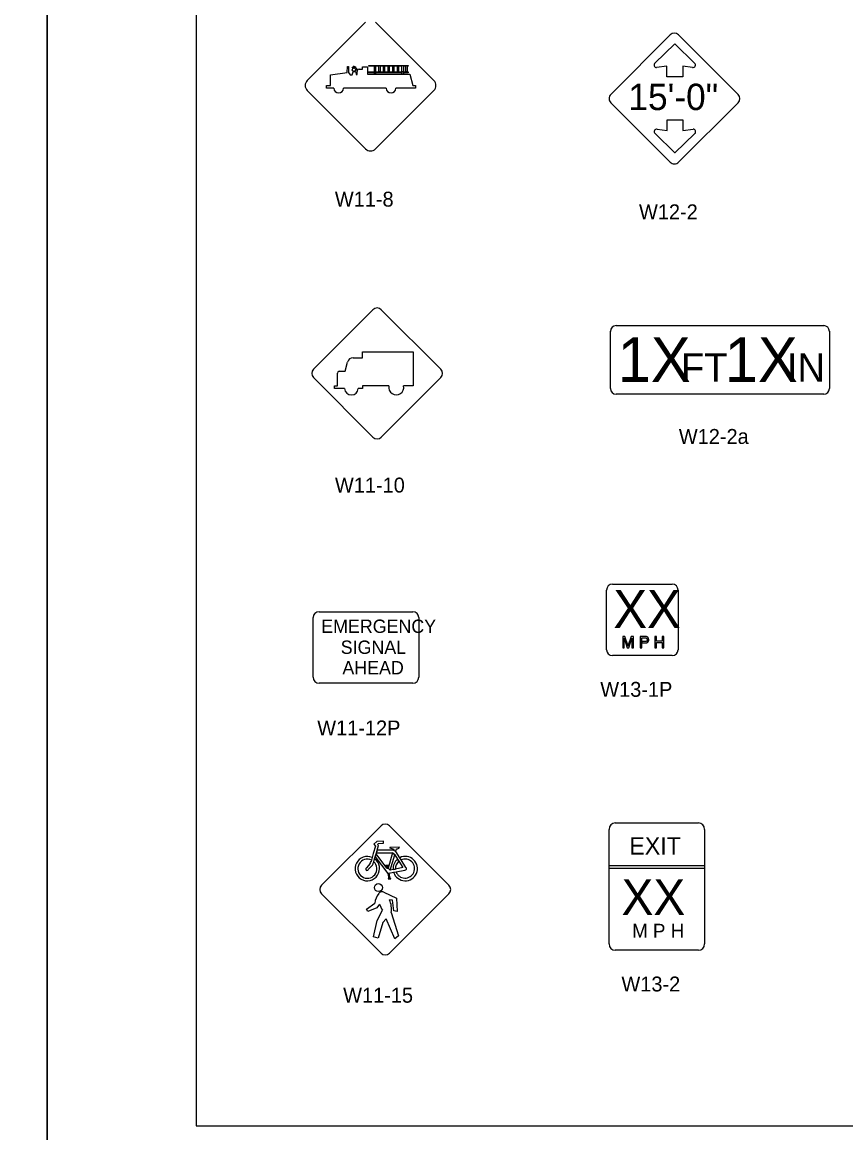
# Model space of a CAD drawing. Extents: x 42133 to 45533, y 41351 to 47951.
# Drawn here: x 43821 to 44235, y 45798 to 46356 of the extents above; entities that cross this region are included whole.
import ezdxf

# ---------------------------------------------------------------- set-up
doc = ezdxf.new("R2010")
doc.units = 0
for name, color, linetype in [('#plot_shape', 7, 'Continuous'), ('P_ODOT_PLAN_Border', 7, 'Continuous'), ('P_TRAF_SIGN_SignDetails', 7, 'Continuous')]:
    doc.layers.add(name, color=color, linetype=linetype)

msp = doc.modelspace()

# ---------------------------------------------------------------- linework, layer by layer
at = {"layer": '#plot_shape'}
for points in [[(42133.34, 45751.35), (43833.34, 45751.35), (43833.34, 46851.35), (42133.34, 46851.35)], [(43833.34, 45751.35), (45533.34, 45751.35), (45533.34, 46851.35), (43833.34, 46851.35)]]:
    msp.add_lwpolyline(points, close=True, dxfattribs=at)
at = {"layer": 'P_ODOT_PLAN_Border'}
msp.add_lwpolyline([(43908.34, 45801.35), (45508.34, 45801.35), (45508.34, 46801.35), (43908.34, 46801.35)], close=True, dxfattribs=at)
at = {"layer": 'P_TRAF_SIGN_SignDetails'}
for p, q in [((43964.13, 46326.71), (43993.42, 46355.98)), ((43964.13, 46326.71), (43993.42, 46355.98)), ((44027.8, 46326.67), (43998.49, 46355.98)), ((44027.8, 46326.67), (43998.49, 46355.98)), ((44116.72, 46319.72), (44146.58, 46349.57)), ((44116.72, 46319.72), (44146.58, 46349.57)), ((44116.72, 46319.72), (44146.58, 46349.57)), ((44116.72, 46319.72), (44146.58, 46349.57)), ((44180.69, 46319.72), (44150.83, 46349.57)), ((44180.69, 46319.72), (44150.83, 46349.57)), ((44180.69, 46319.72), (44150.83, 46349.57)), ((44138.87, 46335.46), (44148.87, 46345.12)), ((44148.85, 46345.09), (44148.9, 46345.09)), ((44148.87, 46345.12), (44158.88, 46335.46)), ((43975.84, 46329.6), (43984.27, 46330.77)), ((43984.27, 46330.77), (43984.42, 46333.74)), ((43984.42, 46333.74), (43984.85, 46333.74)), ((43984.85, 46333.74), (43984.85, 46330.66)), ((43984.85, 46330.66), (43985.68, 46329.55)), ((43986.66, 46333.07), (43986.66, 46333.14)), ((43986.66, 46333.14), (43987.24, 46333.14)), ((43987.25, 46333.07), (43986.66, 46333.07)), ((43986.66, 46329.55), (43987.15, 46331.01)), ((43987.15, 46331.01), (43987.63, 46331.21)), ((43987.24, 46333.14), (43987.24, 46333.79)), ((43987.92, 46331.25), (43987.63, 46331.21)), ((43989.23, 46329.77), (43989.23, 46331.28)), ((43990.17, 46332.38), (43991.85, 46332.38)), ((43991.85, 46332.38), (43991.85, 46333.55)), ((43991.85, 46333.55), (43994.48, 46333.55)), ((43994.48, 46333.55), (43994.48, 46329.85)), ((43994.48, 46329.85), (43997.94, 46329.85)), ((43995.14, 46334.3), (44014.91, 46334.3)), ((43995.14, 46333.81), (43995.14, 46334.3)), ((43997.94, 46333.81), (43995.14, 46333.81)), ((43995.14, 46330.6), (43995.14, 46331.13)), ((43995.14, 46331.13), (43995.14, 46331.12)), ((43995.14, 46331.12), (43997.94, 46331.12)), ((43997.94, 46330.6), (43995.14, 46330.6)), ((43997.94, 46331.12), (43997.94, 46333.81)), ((43998.52, 46331.12), (43997.94, 46331.12)), ((43997.94, 46331.12), (43998.52, 46331.12)), ((43997.94, 46329.85), (43997.94, 46330.6)), ((43997.94, 46329.85), (43998.52, 46329.85)), ((43998.52, 46329.85), (43997.94, 46329.85)), ((44000.16, 46333.81), (43998.52, 46333.81)), ((43998.52, 46333.81), (43998.52, 46331.12)), ((43998.52, 46331.12), (44000.16, 46331.12)), ((44011.75, 46330.6), (43998.52, 46330.6)), ((43998.52, 46330.6), (43998.52, 46329.85)), ((43998.52, 46329.85), (44011.75, 46329.85)), ((44000.16, 46331.12), (44000.16, 46333.81)), ((44000.75, 46331.12), (44000.16, 46331.12)), ((44000.16, 46331.12), (44000.75, 46331.12)), ((44002.45, 46333.81), (44000.75, 46333.81)), ((44000.75, 46333.81), (44000.75, 46331.12)), ((44000.75, 46331.12), (44002.45, 46331.12)), ((44002.45, 46331.12), (44002.45, 46333.81)), ((44003.03, 46331.12), (44002.45, 46331.12)), ((44002.45, 46331.12), (44003.03, 46331.12)), ((44004.79, 46333.81), (44003.03, 46333.81)), ((44003.03, 46333.81), (44003.03, 46331.12)), ((44003.03, 46331.12), (44004.79, 46331.12)), ((44004.79, 46331.12), (44004.79, 46333.81)), ((44005.37, 46331.12), (44004.79, 46331.12)), ((44004.79, 46331.12), (44005.37, 46331.12)), ((44007.12, 46333.81), (44005.37, 46333.81)), ((44005.37, 46333.81), (44005.37, 46331.12)), ((44005.37, 46331.12), (44007.12, 46331.12)), ((44007.12, 46331.12), (44007.12, 46333.81)), ((44007.66, 46331.12), (44007.12, 46331.12)), ((44007.12, 46331.12), (44007.66, 46331.12)), ((44009.46, 46333.81), (44007.66, 46333.81)), ((44007.66, 46333.81), (44007.66, 46331.12)), ((44007.66, 46331.12), (44009.46, 46331.12)), ((44009.46, 46331.12), (44009.46, 46333.81)), ((44010.05, 46331.12), (44009.46, 46331.12)), ((44009.46, 46331.12), (44010.05, 46331.12)), ((44011.75, 46333.81), (44010.05, 46333.81)), ((44010.05, 46333.81), (44010.05, 46331.12)), ((44010.05, 46331.12), (44011.75, 46331.12)), ((44011.75, 46331.12), (44011.75, 46333.81)), ((44012.44, 46331.12), (44011.75, 46331.12)), ((44011.75, 46331.12), (44012.44, 46331.12)), ((44011.75, 46329.85), (44011.75, 46330.6)), ((44011.75, 46329.85), (44012.44, 46329.85)), ((44012.44, 46329.85), (44011.75, 46329.85)), ((44013.71, 46333.81), (44012.44, 46333.81)), ((44012.44, 46333.81), (44012.44, 46331.12)), ((44012.44, 46331.12), (44013.71, 46331.12)), ((44014.92, 46330.6), (44012.44, 46330.6)), ((44012.44, 46330.6), (44012.44, 46329.85)), ((44012.44, 46329.85), (44015.66, 46329.85)), ((44013.71, 46331.12), (44013.71, 46333.81)), ((44014.29, 46331.12), (44013.71, 46331.12)), ((44013.71, 46331.12), (44014.29, 46331.12)), ((44014.91, 46333.81), (44014.29, 46333.81)), ((44014.29, 46333.81), (44014.29, 46331.12)), ((44014.29, 46331.12), (44014.92, 46331.12)), ((44014.91, 46334.3), (44014.91, 46333.81)), ((44014.92, 46331.12), (44014.92, 46330.6)), ((44015.66, 46329.85), (44017.25, 46324.24)), ((44144.89, 46333.94), (44139.77, 46333.22)), ((44144.89, 46328.57), (44144.89, 46333.94)), ((44157.78, 46333.23), (44152.85, 46333.94)), ((44152.85, 46333.94), (44152.85, 46328.57)), ((43973.83, 46322.85), (43973.83, 46324.24)), ((43973.83, 46324.24), (43975.84, 46324.24)), ((43975.84, 46324.24), (43975.84, 46329.6)), ((43985.68, 46329.55), (43986.66, 46329.55)), ((43988.75, 46329.78), (43989.23, 46329.77)), ((44017.25, 46324.24), (44018.51, 46324.24)), ((44018.51, 46324.24), (44018.51, 46322.85)), ((44152.85, 46328.57), (44144.89, 46328.57)), ((43993.44, 46292.31), (43964.13, 46321.61)), ((43993.44, 46292.31), (43964.13, 46321.61)), ((43977.51, 46322.85), (43973.83, 46322.85)), ((44003.82, 46322.85), (43982.38, 46322.85)), ((43998.52, 46292.31), (44027.8, 46321.59)), ((43998.52, 46292.31), (44027.8, 46321.59)), ((44018.51, 46322.85), (44008.69, 46322.85)), ((44146.58, 46285.62), (44116.72, 46315.47)), ((44146.58, 46285.62), (44116.72, 46315.47)), ((44146.58, 46285.62), (44116.72, 46315.47)), ((44180.69, 46315.47), (44150.83, 46285.62)), ((44180.69, 46315.47), (44150.83, 46285.62)), ((44180.69, 46315.47), (44150.83, 46285.62)), ((44140.06, 46302.21), (44145, 46301.5)), ((44145, 46306.88), (44152.95, 46306.88)), ((44145, 46301.5), (44145, 46306.88)), ((44152.95, 46306.88), (44152.95, 46301.5)), ((44152.95, 46301.5), (44158.08, 46302.23)), ((44148.98, 46290.33), (44138.97, 46299.98)), ((44158.99, 46299.98), (44148.98, 46290.33)), ((44149.01, 46290.35), (44148.95, 46290.35)), ((43967.23, 46181.6), (43997.11, 46211.48)), ((44001.36, 46211.48), (44031.25, 46181.61)), ((44119.39, 46203.49), (44223.75, 46203.49)), ((44116.51, 46171.87), (44116.51, 46200.62)), ((44226.61, 46200.62), (44226.61, 46171.87)), ((43967.23, 46177.34), (43997.11, 46147.47)), ((44031.25, 46177.34), (44001.36, 46147.47)), ((44223.75, 46169), (44119.39, 46169)), ((44117.59, 46073.58), (44147.56, 46073.58)), ((44114.59, 46040.61), (44114.59, 46070.58)), ((44150.55, 46070.58), (44150.55, 46040.61)), ((43967.08, 46026.77), (43967.08, 46056.71)), ((43970.08, 46059.71), (44017.2, 46059.71)), ((44020.19, 46056.71), (44020.19, 46026.77)), ((44147.56, 46037.61), (44117.59, 46037.61)), ((44017.2, 46023.78), (43970.08, 46023.78)), ((43971.33, 45922.19), (44001.21, 45952.07)), ((44005.47, 45952.07), (44035.35, 45922.2)), ((44115.9, 45892.73), (44115.9, 45950.31)), ((44118.9, 45953.5), (44160.87, 45953.5)), ((44163.87, 45950.31), (44163.87, 45892.73)), ((43998.48, 45941.84), (43997.33, 45938.1)), ((43999.06, 45944.24), (43997.67, 45942.8)), ((43997.67, 45942.8), (43998.48, 45941.84)), ((43998.86, 45938.52), (43999.27, 45939.85)), ((43999.27, 45939.85), (43998.86, 45938.52)), ((44002.44, 45944.44), (43999.06, 45944.24)), ((43999.27, 45939.85), (43999.98, 45942.15)), ((44007.45, 45939.81), (43999.27, 45939.85)), ((43999.49, 45942.74), (43999.97, 45943.24)), ((43999.98, 45942.15), (43999.49, 45942.74)), ((43999.97, 45943.24), (44002.51, 45943.4)), ((44002.51, 45943.4), (44002.44, 45944.44)), ((44010.44, 45941.42), (44005.75, 45941.16)), ((44007.61, 45940.39), (44007.45, 45939.81)), ((44007.45, 45939.81), (44008.7, 45939.25)), ((44008.7, 45939.25), (44007.45, 45939.81)), ((44008.7, 45939.25), (44009.02, 45940.47)), ((44010.72, 45935.99), (44008.7, 45939.25)), ((44010.44, 45941.42), (44010.44, 45941.42)), ((43996.41, 45934.8), (43996.22, 45934.12)), ((43996.8, 45936.19), (43996.41, 45934.8)), ((43997.33, 45938.09), (43996.8, 45936.19)), ((43997.47, 45933.62), (43997.58, 45934.02)), ((43997.58, 45934.02), (43997.99, 45935.49)), ((43997.6, 45934.02), (43997.99, 45935.49)), ((43997.99, 45935.5), (43998.26, 45936.43)), ((43998.26, 45936.43), (43998.71, 45938.03)), ((43998.71, 45938.03), (43998.26, 45936.43)), ((43998.26, 45936.43), (44004.58, 45928.16)), ((43998.71, 45938.03), (43998.86, 45938.52)), ((44004.2, 45930.86), (43998.71, 45938.03)), ((43998.86, 45938.52), (44007.06, 45938.47)), ((44007.06, 45938.47), (44004.74, 45930.81)), ((44005.83, 45929.78), (44008.18, 45937.51)), ((44008.18, 45937.51), (44007.06, 45938.47)), ((44007.06, 45938.47), (44008.18, 45937.51)), ((44008.18, 45937.51), (44009.57, 45935.29)), ((44009.54, 45935.33), (44010.21, 45934.24)), ((44009.57, 45935.29), (44010.21, 45934.27)), ((44010.21, 45934.27), (44009.57, 45935.29)), ((44010.21, 45934.27), (44012.21, 45931.05)), ((44010.21, 45934.24), (44010.21, 45934.27)), ((44011.35, 45934.97), (44010.72, 45935.99)), ((44011.35, 45934.97), (44010.72, 45935.99)), ((44013.71, 45931.18), (44011.35, 45934.97)), ((44011.36, 45934.96), (44011.35, 45934.97)), ((43995.75, 45933.06), (43993.85, 45930.97)), ((43994.83, 45930.04), (43996.87, 45932.3)), ((44004.97, 45932.21), (44003.52, 45932.21)), ((44003.52, 45932.21), (44003.52, 45931.91)), ((44003.52, 45931.91), (44004, 45931.91)), ((44004, 45931.91), (44004.2, 45930.86)), ((44004.2, 45930.86), (44004.74, 45930.81)), ((44004.74, 45930.81), (44004.2, 45930.86)), ((44004.74, 45930.81), (44004.52, 45931.91)), ((44004.52, 45931.91), (44004.97, 45931.91)), ((44004.69, 45928.18), (44004.58, 45928.16)), ((44005.25, 45928.29), (44004.69, 45928.18)), ((44004.69, 45928.18), (44005.18, 45925.64)), ((44004.74, 45930.81), (44005.83, 45929.78)), ((44005.83, 45929.78), (44004.74, 45930.81)), ((44004.97, 45931.91), (44004.97, 45932.21)), ((44005.25, 45928.29), (44007.54, 45928.75)), ((44005.76, 45925.66), (44005.25, 45928.29)), ((44007.27, 45930.06), (44005.83, 45929.78)), ((44008.5, 45930.31), (44007.27, 45930.06)), ((44007.27, 45930.06), (44008.5, 45930.31)), ((44007.54, 45928.75), (44008.78, 45928.99)), ((44007.54, 45928.75), (44008.78, 45928.99)), ((44012.21, 45931.05), (44008.5, 45930.31)), ((44008.78, 45928.99), (44013.13, 45929.86)), ((44115.9, 45932.2), (44163.87, 45932.2)), ((44115.9, 45930.87), (44163.87, 45930.87)), ((44005.18, 45925.64), (44004.75, 45925.64)), ((44004.75, 45925.64), (44004.75, 45925.4)), ((44004.75, 45925.4), (44006.18, 45925.4)), ((44006.18, 45925.66), (44005.76, 45925.66)), ((44006.18, 45925.4), (44006.18, 45925.66)), ((43971.33, 45917.93), (44001.21, 45888.06)), ((44002.69, 45918.68), (44002.69, 45918.69)), ((44002.69, 45918.69), (44008.95, 45915.7)), ((44002.69, 45918.68), (44002.69, 45918.69)), ((44002.69, 45918.68), (44002.69, 45918.69)), ((44002.69, 45918.69), (44008.95, 45915.7)), ((44002.69, 45918.68), (44002.69, 45918.69)), ((44035.35, 45917.93), (44005.47, 45888.06)), ((43993.84, 45910.16), (43998.12, 45913.25)), ((43993.84, 45910.16), (43998.12, 45913.25)), ((44000.42, 45912.78), (43999.16, 45910.85)), ((44000.42, 45912.78), (43999.16, 45910.85)), ((44006.96, 45914.7), (44005.46, 45914.81)), ((44006.96, 45914.7), (44005.46, 45914.81)), ((44007.67, 45909.28), (44006.96, 45914.7)), ((44007.67, 45909.28), (44006.96, 45914.7)), ((44008.95, 45915.7), (44009.27, 45909.01)), ((44008.95, 45915.7), (44009.27, 45909.01)), ((43994.59, 45909.03), (43993.84, 45910.16)), ((43994.59, 45909.03), (43993.84, 45910.16)), ((43999.16, 45910.85), (43994.59, 45909.03)), ((43999.16, 45910.85), (43994.59, 45909.03)), ((43999.31, 45904.49), (44001.89, 45909.66)), ((43999.31, 45904.49), (44001.89, 45909.66)), ((44006.35, 45908.51), (44010.04, 45896.74)), ((44006.35, 45908.51), (44010.04, 45896.74)), ((44009.27, 45909.01), (44007.67, 45909.28)), ((44009.27, 45909.01), (44007.67, 45909.28)), ((43997.35, 45896.32), (43999.31, 45904.49)), ((43997.35, 45896.32), (43999.31, 45904.49)), ((44002.08, 45903.56), (43999.77, 45895.62)), ((44002.08, 45903.56), (43999.77, 45895.62)), ((44003.74, 45905.33), (44002.08, 45903.56)), ((44003.74, 45905.33), (44002.08, 45903.56)), ((44008.1, 45895.26), (44003.74, 45905.33)), ((44008.1, 45895.26), (44003.74, 45905.33)), ((43999.77, 45895.62), (43997.35, 45896.32)), ((43999.77, 45895.62), (43997.35, 45896.32)), ((44010.04, 45896.74), (44008.1, 45895.26)), ((44010.04, 45896.74), (44008.1, 45895.26)), ((44160.87, 45889.54), (44118.9, 45889.54))]:
    msp.add_line(p, q, dxfattribs=at)
for points in [[(43987.14, 46187.31), (43991.85, 46187.31), (43991.85, 46190.27), (44017.34, 46190.27), (44017.34, 46173.26), (44012.59, 46173.26)], [(43987.14, 46187.31), (43991.85, 46187.31), (43991.85, 46190.27), (44017.34, 46190.27), (44017.34, 46173.26), (44012.59, 46173.26)], [(43987.14, 46187.31), (43991.85, 46187.31), (43991.85, 46190.27), (44017.34, 46190.27), (44017.34, 46173.26), (44012.59, 46173.26)], [(43983.22, 46180.53), (43984.42, 46185.19)], [(43983.22, 46180.53), (43984.42, 46185.19)], [(43983.22, 46180.53), (43984.42, 46185.19)], [(43982.9, 46171.87), (43977.88, 46171.87), (43977.88, 46173.26), (43979.27, 46173.26), (43979.27, 46179.66)], [(43982.9, 46171.87), (43977.88, 46171.87), (43977.88, 46173.26), (43979.27, 46173.26), (43979.27, 46179.66)], [(43982.9, 46171.87), (43977.88, 46171.87), (43977.88, 46173.26), (43979.27, 46173.26), (43979.27, 46179.66)], [(43980.14, 46180.53), (43983.22, 46180.53)], [(43980.14, 46180.53), (43983.22, 46180.53)], [(43980.14, 46180.53), (43983.22, 46180.53)], [(44005.19, 46173.26), (43991.85, 46173.26), (43991.85, 46171.87), (43989.8, 46171.87)], [(44005.19, 46173.26), (43991.85, 46173.26), (43991.85, 46171.87), (43989.8, 46171.87)], [(44005.19, 46173.26), (43991.85, 46173.26), (43991.85, 46171.87), (43989.8, 46171.87)]]:
    msp.add_lwpolyline(points, dxfattribs=at)
for points in [[(44122.76, 46047.23), (44122.76, 46041.59), (44123.47, 46041.59), (44123.47, 46046.41), (44123.52, 46046.16), (44123.59, 46045.91), (44125.02, 46041.59), (44125.74, 46041.59), (44127.19, 46045.91), (44127.27, 46046.16), (44127.33, 46046.41), (44127.33, 46041.59), (44128.08, 46041.59), (44128.08, 46047.23), (44126.98, 46047.23), (44125.53, 46042.92), (44125.46, 46042.68), (44125.4, 46042.44), (44125.34, 46042.68), (44125.26, 46042.92), (44123.86, 46047.23)], [(44135.78, 46045.61), (44135.77, 46045.79), (44135.75, 46045.97), (44135.73, 46046.09), (44135.69, 46046.21), (44135.65, 46046.33), (44135.59, 46046.44), (44135.53, 46046.55), (44135.46, 46046.65), (44135.38, 46046.75), (44135.29, 46046.83), (44135.2, 46046.91), (44135.1, 46046.97), (44135, 46047.03), (44134.89, 46047.08), (44134.78, 46047.13), (44134.67, 46047.16), (44134.56, 46047.19), (44134.44, 46047.2), (44134.21, 46047.22), (44133.97, 46047.23), (44133.74, 46047.24), (44133.5, 46047.23), (44131.52, 46047.23), (44131.52, 46041.59), (44132.29, 46041.59), (44132.29, 46043.97), (44132.29, 46044.64), (44132.29, 46046.54), (44133.75, 46046.54), (44133.98, 46046.54), (44134.22, 46046.52), (44134.33, 46046.5), (44134.43, 46046.47), (44134.53, 46046.43), (44134.63, 46046.38), (44134.69, 46046.33), (44134.75, 46046.28), (44134.8, 46046.22), (44134.85, 46046.15), (44134.89, 46046.08), (44134.93, 46046.01), (44134.95, 46045.94), (44134.97, 46045.86), (44134.99, 46045.73), (44135, 46045.59)], [(44135, 46045.59), (44134.99, 46045.48), (44134.98, 46045.37), (44134.95, 46045.26), (44134.92, 46045.15), (44134.88, 46045.08), (44134.84, 46045.01), (44134.79, 46044.95), (44134.73, 46044.89), (44134.67, 46044.83), (44134.6, 46044.79), (44134.52, 46044.75), (44134.45, 46044.72), (44134.35, 46044.69), (44134.25, 46044.67), (44134.15, 46044.66), (44134.05, 46044.65), (44133.69, 46044.64), (44132.29, 46044.64), (44132.29, 46043.97), (44133.56, 46043.97), (44133.79, 46043.97), (44134.02, 46043.97), (44134.25, 46043.99), (44134.48, 46044.01), (44134.58, 46044.02), (44134.67, 46044.05), (44134.77, 46044.08), (44134.86, 46044.11), (44134.95, 46044.16), (44135.04, 46044.2), (44135.12, 46044.26), (44135.2, 46044.32), (44135.28, 46044.38), (44135.35, 46044.45), (44135.42, 46044.52), (44135.48, 46044.6), (44135.54, 46044.68), (44135.59, 46044.77), (44135.63, 46044.86), (44135.67, 46044.95), (44135.72, 46045.11), (44135.76, 46045.27), (44135.78, 46045.44), (44135.78, 46045.61)], [(44138.89, 46047.23), (44138.89, 46041.59), (44139.66, 46041.59), (44139.66, 46044.23), (44142.58, 46044.23), (44142.58, 46041.59), (44143.35, 46041.59), (44143.35, 46047.23), (44142.58, 46047.23), (44142.58, 46044.92), (44139.66, 46044.92), (44139.66, 46047.23)]]:
    msp.add_lwpolyline(points, close=True, dxfattribs=at)
for centre, radius in [((43987.63, 46332.12), 0.912), ((43999.9, 45921.04), 1.99), ((43999.9, 45921.04), 1.99)]:
    msp.add_circle(centre, radius, dxfattribs=at)
for centre, radius, start, end in [((44148.7, 46347.45), 3.01, 45.0123, 135), ((44148.7, 46347.45), 3.01, 45.0123, 135), ((44148.7, 46347.45), 3.01, 45.0123, 135), ((44139.78, 46334.53), 1.31, 134.5654, 269.4571), ((44157.99, 46334.51), 1.3, 260.6138, 47.0765), ((43987.23, 46331.87), 1.92, 62.2077, 89.7198), ((43987.41, 46331.73), 1.35, 48.8563, 96.7723), ((43987.64, 46332.46), 1.2, 20.9778, 66.1816), ((43990.4, 46334.8), 2.95, 224.2826, 235.5587), ((43989.23, 46332.97), 0.781, 230.6215, 276.0783), ((43990.54, 46333.73), 1.96, 205.2633, 231.4034), ((43990.35, 46331.27), 1.12, 99.3655, 179.409), ((43966.67, 46324.16), 3.59, 135, 225), ((44025.26, 46324.13), 3.59, 315, 44.9682), ((44025.26, 46324.13), 3.59, 315, 44.9682), ((43979.95, 46322.87), 2.44, 180.5304, 359.4696), ((44006.26, 46322.87), 2.44, 180.5304, 359.4696), ((44118.85, 46317.59), 3.01, 135, 225.0172), ((44118.85, 46317.59), 3.01, 135, 225.0172), ((44118.85, 46317.59), 3.01, 135, 225.0172), ((44178.56, 46317.59), 3.01, 315, 44.9762), ((44178.56, 46317.59), 3.01, 315, 44.9762), ((44178.56, 46317.59), 3.01, 315, 44.9762), ((44139.85, 46300.94), 1.3, 80.6138, 227.0765), ((44158.07, 46300.92), 1.31, 314.5654, 89.4571), ((43995.98, 46294.85), 3.59, 225, 315), ((43995.98, 46294.85), 3.59, 225, 315), ((44148.7, 46287.74), 3.01, 224.9829, 315), ((44148.7, 46287.74), 3.01, 224.9829, 315), ((44148.7, 46287.74), 3.01, 224.9829, 315), ((43999.24, 46209.35), 3.01, 45, 135), ((44119.39, 46200.61), 2.87, 90, 180), ((44223.75, 46200.61), 2.87, 360, 90), ((43987.14, 46184.5), 2.81, 90, 165.6233), ((43987.14, 46184.5), 2.81, 90, 165.6233), ((43987.14, 46184.5), 2.81, 90, 165.6233), ((43969.36, 46179.47), 3.01, 135, 225), ((43980.14, 46179.66), 0.865, 90, 180), ((43980.14, 46179.66), 0.865, 90, 180), ((43980.14, 46179.66), 0.865, 90, 180), ((44029.11, 46179.47), 3.01, 315, 45), ((43986.35, 46172.14), 3.46, 184.4504, 355.5496), ((43986.35, 46172.14), 3.46, 184.4504, 355.5496), ((43986.35, 46172.14), 3.46, 184.4504, 355.5496), ((44008.89, 46172.46), 3.79, 167.8159, 12.1841), ((44008.89, 46172.46), 3.79, 167.8159, 12.1841), ((44008.89, 46172.46), 3.79, 167.8159, 12.1841), ((44119.39, 46171.87), 2.87, 180, 270), ((44223.75, 46171.87), 2.87, 270, 360), ((43999.24, 46149.6), 3.01, 225, 315), ((44117.6, 46070.58), 3, 90, 180), ((44147.57, 46070.58), 3, 0, 90), ((43970.08, 46056.71), 2.99, 90, 180), ((44017.2, 46056.71), 2.99, 360, 90), ((44117.6, 46040.6), 3, 180, 270), ((44147.57, 46040.6), 3, 270, 0), ((43970.08, 46026.77), 2.99, 180, 270), ((44017.2, 46026.77), 2.99, 270, 360), ((44003.34, 45949.94), 3.01, 45, 135), ((44005.8, 45941.03), 0.122, 98.1714, 240.5811), ((44008.8, 45947.99), 7.68, 246.229, 261.1184), ((44009.12, 45942.09), 1.63, 266.6391, 329.7311), ((44010.42, 45941.32), 0.106, 336.8194, 78.5167), ((43994.34, 45930.57), 6.13, 66.4023, 53.4605), ((43994.35, 45930.51), 4.79, 64.4104, 47.1387), ((43970.21, 45944.99), 28.19, 334.9582, 337.3217), ((43971.46, 45944.49), 28.19, 334.4184, 337.3217), ((44013.4, 45930.56), 6.13, 129.013, 184.6549), ((44013.4, 45930.56), 6.13, 197.6727, 116.3307), ((44013.29, 45930.58), 4.79, 129.9972, 183.4253), ((44013.29, 45930.58), 4.79, 199.3058, 113.7924), ((43994.21, 45930.36), 0.688, 122.8763, 330.7719), ((44013.29, 45930.58), 0.732, 257.4123, 57.0678), ((43973.46, 45920.06), 3.01, 135, 225), ((44007.26, 45912.31), 9.19, 141.4976, 174.1516), ((44007.26, 45912.31), 9.19, 141.4976, 174.1516), ((44002.78, 45916.17), 3.29, 133.0399, 145.5045), ((44002.78, 45916.17), 3.29, 133.0399, 145.5045), ((44001.7, 45916.92), 2.02, 60.6785, 125.4757), ((44001.7, 45916.92), 2.02, 60.6785, 125.4757), ((44033.22, 45920.06), 3.01, 315, 45), ((44026.86, 45923.34), 28.46, 201.7818, 208.7113), ((44026.86, 45923.34), 28.46, 201.7818, 208.7113), ((43996.2, 45910.29), 10.29, 349.9861, 26.0599), ((43996.2, 45910.29), 10.29, 349.9861, 26.0599), ((44003.34, 45890.18), 3.01, 225, 315)]:
    msp.add_arc(centre, radius, start, end, dxfattribs=at)
for centre, major_axis, start_param, end_param in [((44118.9, 45950.3), (0, 3.2), 0, 1.570796), ((44160.86, 45950.3), (0, 3.2), 4.712389, 6.283185), ((44118.9, 45892.74), (0, -3.2), 4.712389, 6.283185), ((44160.86, 45892.74), (0, 3.2), 3.141593, 4.712389)]:
    msp.add_ellipse(centre, major_axis=major_axis, ratio=0.9371, start_param=start_param, end_param=end_param, dxfattribs=at)
msp.add_spline([(43987.92, 46331.25), (43988.17, 46331.21), (43988.75, 46329.78)], degree=3, dxfattribs=at)

# ---------------------------------------------------------------- texts
for s, height, p in [('15\'-0"', 13.244, (44125.58, 46311.83)), ('W11-8', 7.5, (43978.01, 46263.29)), ('W12-2', 7.5, (44130.9, 46256.92)), ('1X', 22.423, (44120.19, 46175.21)), ('1X', 22.423, (44174, 46175.21)), ('FT', 14.305, (44151.98, 46175.26)), ('IN', 14.305, (44205.28, 46175.26)), ('W12-2a', 7.5, (44150.93, 46144.02)), ('W11-10', 7.5, (43978.05, 46119.59)), ('EMERGENCY', 6.698, (43971.17, 46049.04)), ('SIGNAL', 6.698, (43980.96, 46038.5)), ('AHEAD', 6.698, (43981.8, 46028.21)), ('W13-1P', 7.5, (44111.43, 46016.91)), ('W11-12P', 7.5, (43969.16, 45997.51)), ('EXIT', 8.699, (44126.05, 45937.66)), ('XX', 17.955, (44122.11, 45907.28)), ('M P H', 7.036, (44127.46, 45895.78)), ('W13-2', 7.5, (44122.08, 45868.82)), ('W11-15', 7.5, (43982.18, 45863.18))]:
    msp.add_text(s, height=height, dxfattribs=at).set_placement(p)
msp.add_text('XX', height=18.954, rotation=0, dxfattribs=at).set_placement((44118.04, 46051.57))

doc.saveas('drawing.dxf')
